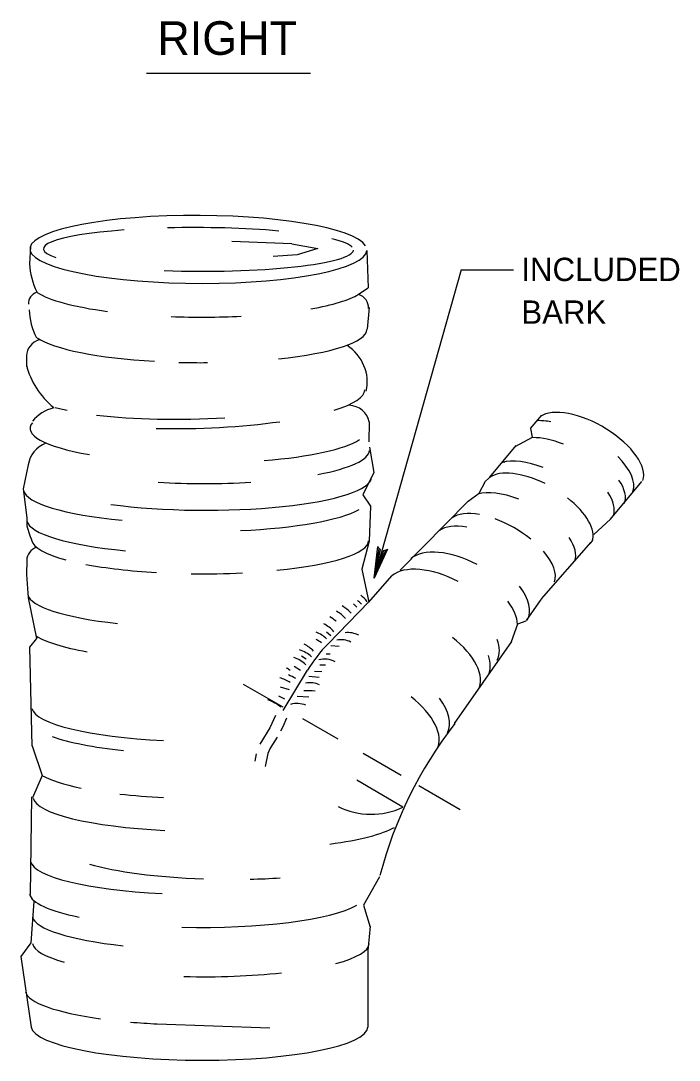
# Model space of a CAD drawing. Extents: x 639115 to 640019, y 298285 to 298879.
# Drawn here: x 639717.2 to 639801.9, y 298555.3 to 298689.1 of the extents above; entities that cross this region are included whole.
import ezdxf

# ---------------------------------------------------------------- set-up
doc = ezdxf.new("R2010")
doc.units = 0
doc.layers.add('1', color=7, linetype='Continuous')

msp = doc.modelspace()

# ---------------------------------------------------------------- linework, layer by layer
at = {"layer": '1'}
for p, q in [((639733.43, 298682.34), (639754.53, 298682.34)), ((639752.13, 298660.35), (639744.38, 298660.67)), ((639773.91, 298657.04), (639762.7, 298617.37)), ((639773.91, 298657.04), (639780.61, 298657.04)), ((639760.69, 298653.88), (639761.95, 298654.7)), ((639782.81, 298636.59), (639784.26, 298638.32)), ((639783.07, 298635.51), (639782.84, 298636.61)), ((639780.86, 298634.29), (639783.07, 298635.51)), ((639777.59, 298630.35), (639780.99, 298634.41)), ((639793.1, 298624.94), (639797.15, 298629.78)), ((639793.1, 298624.94), (639790.95, 298622.98)), ((639784.23, 298614.69), (639790.62, 298621.99)), ((639790.48, 298621.8), (639790.82, 298622.21)), ((639756.77, 298608.92), (639762, 298614.3)), ((639760.05, 298614.05), (639760.49, 298613.63)), ((639782.3, 298611.91), (639784.19, 298614.63)), ((639780.36, 298609.19), (639781.17, 298611.47)), ((639781.17, 298611.47), (639782.25, 298611.88)), ((639756.59, 298610.47), (639757.13, 298609.99)), ((639757.11, 298608.68), (639758.19, 298608.61)), ((639773.06, 298598.64), (639780.4, 298609.19)), ((639753.36, 298607.36), (639753.96, 298606.98)), ((639756.51, 298607.62), (639757.03, 298607.62)), ((639752.4, 298606.05), (639753.21, 298605.52)), ((639755.73, 298606.21), (639756.44, 298606.21)), ((639750.99, 298600.32), (639754.14, 298605.54)), ((639754.29, 298604.74), (639755.62, 298604.64)), ((639755.01, 298605.41), (639755.98, 298605.33)), ((639750.98, 298600.76), (639745.9, 298603.69)), ((639750.59, 298603.38), (639751.76, 298603.05)), ((639750.38, 298602.21), (639751.15, 298601.83)), ((639752.79, 298602.17), (639754.3, 298602.11)), ((639758.07, 298596.66), (639753.54, 298599.27)), ((639766.16, 298591.98), (639761.28, 298594.79)), ((639766.41, 298587.88), (639760.46, 298591.38)), ((639773.77, 298587.57), (639768.45, 298590.65)), ((639763.37, 298578.93), (639761.34, 298575.27)), ((639761.34, 298575.27), (639762.2, 298572.46)), ((639734.8, 298560.02), (639749.29, 298559.49))]:
    msp.add_line(p, q, dxfattribs=at)
for points in [[(639718.47, 298660.01), (639718.38, 298657.8)], [(639752.13, 298660.35), (639755.46, 298659.76), (639752.78, 298658.96), (639749.69, 298658.74)], [(639761.77, 298659.49), (639761.95, 298654.7)], [(639762.04, 298652.18), (639761.79, 298649.37)], [(639717.96, 298645.97), (639717.98, 298644.54)], [(639762.06, 298637.46), (639762.03, 298634.9)], [(639762.1, 298634.21), (639762.66, 298630.96), (639761.25, 298628.06), (639762.23, 298626.64), (639762.06, 298622.13), (639761.12, 298618.51), (639762.02, 298614.29)], [(639718.21, 298631.94), (639717.55, 298628.84), (639718.01, 298625.13), (639718.01, 298624.03)], [(639766.05, 298618.38), (639774.81, 298627.25), (639776.23, 298628.27), (639777.04, 298629.82), (639777.79, 298630.52)], [(639764.21, 298620.95), (639763.9, 298620.89), (639762.7, 298617.37), (639764.21, 298620.95), (639764.43, 298621.09), (639762.7, 298617.37), (639763.53, 298620.99), (639763.3, 298621.19), (639762.7, 298617.37), (639763.18, 298621.45), (639763.3, 298621.19)], [(639718, 298619.66), (639717.99, 298617.81), (639718.19, 298614.81), (639719.27, 298609.6), (639718.37, 298608.46), (639718.68, 298595.76)], [(639762.02, 298614.29), (639764.97, 298617.66)], [(639750.03, 298599.68), (639749.28, 298598.11), (639748, 298595.98)], [(639751.41, 298599.35), (639750.97, 298598.21), (639750.67, 298597.68)], [(639750.22, 298596.89), (639749.32, 298595.5), (639749.02, 298594.82), (639748.67, 298593.14)], [(639718.71, 298595.77), (639720.01, 298591.95), (639718.75, 298589.1)], [(639747.53, 298594.76), (639747.34, 298593.83)], [(639718.61, 298589.22), (639718.44, 298576.65)], [(639718.93, 298575.76), (639718.53, 298570.43), (639717.24, 298568.68), (639718.56, 298559.6)], [(639761.88, 298568.99), (639761.88, 298559.6)]]:
    msp.add_lwpolyline(points, dxfattribs=at)
for centre, major_axis, ratio, start_param, end_param in [((639740.09, 298659.65), (21.67, -0.08), 0.201648, 0.122701, 6.273719), ((639740.09, 298659.65), (19.94, -0.07), 0.140896, 2.070785, 3.54742), ((639740.09, 298659.65), (19.94, -0.07), 0.140896, 1.026558, 1.771582), ((639740.09, 298659.65), (19.94, -0.07), 0.140896, 0.122755, 0.53432), ((639740.09, 298659.65), (19.94, -0.07), 0.140896, 4.489929, 6.273772), ((639728.49, 298658.02), (-10.11, 0), 0.9025, 0.023891, 0.433959), ((639719.9, 298652.73), (-1.67, 0), 0.9025, 5.088241, 6.356756), ((639740.1, 298655.31), (21.67, -0.08), 0.201648, 3.437197, 4.143226), ((639740.1, 298655.31), (21.67, -0.08), 0.201648, 5.442821, 5.966342), ((639759.97, 298652.19), (2, 0), 0.9025, 6.209615, 7.47813), ((639728.44, 298652.11), (-10.11, 0), 0.9025, 0.023891, 0.433959), ((639740.1, 298655.31), (21.67, -0.08), 0.201648, 4.549477, 4.968721), ((639740.1, 298649.45), (21.67, -0.08), 0.201648, 5.20727, 6.273719), ((639720.45, 298645.92), (-2.48, 0), 0.9025, 5.058523, 6.264565), ((639740.1, 298649.45), (21.67, -0.08), 0.201648, 3.432131, 4.449047), ((639755.3, 298642.6), (6.52, 0), 0.9025, 6.079323, 7.21363), ((639729, 298646.9), (-11.27, 0), 0.9025, 0.209985, 0.841717), ((639740.1, 298649.45), (21.67, -0.08), 0.201648, 4.596429, 4.766623), ((639739.84, 298641), (21.66, 0.6), 0.201683, 5.665679, 6.275226), ((639722.79, 298634.96), (-4.94, 0), 0.9025, 4.977364, 5.666936), ((639739.78, 298642.21), (21.66, 0.6), 0.201683, 3.716025, 3.83676), ((639759.29, 298637.09), (2.8, 0), 0.9025, 0.147707, 1.509991), ((639790.34, 298633.6), (6.79, -3.97), 0.467565, 0.082974, 2.935197), ((639739.78, 298642.21), (21.66, 0.6), 0.201683, 4.074018, 4.879012), ((639740.1, 298636.54), (21.67, -0.08), 0.201648, 2.973143, 4.010085), ((639739.84, 298641), (21.66, 0.6), 0.201683, 4.464238, 5.224131), ((639788, 298632.54), (6.79, -3.97), 0.467565, 2.208713, 2.489954), ((639740.1, 298636.54), (21.67, -0.08), 0.201648, 5.113839, 5.986294), ((639787.37, 298630.35), (6.79, -3.97), 0.467565, 1.880941, 2.489954), ((639722.07, 298631.52), (-3.89, 0), 0.9025, 5.133197, 6.163121), ((639740.43, 298633.9), (21.67, -0.08), 0.201648, 5.479737, 6.273719), ((639784.76, 298627.34), (6.79, -3.97), 0.467565, 1.880941, 2.748947), ((639789.08, 298632.22), (6.79, -3.97), 0.467565, 0.082974, 1.055649), ((639783.85, 298625.79), (6.79, -3.97), 0.467565, 1.718853, 2.935197), ((639779.99, 298631.8), (-0.72, 0), 0.9025, 5.534807, 5.562504), ((639740.7, 298630.46), (21.67, -0.08), 0.201648, 4.132872, 6.273719), ((639788, 298630.67), (6.79, -3.97), 0.467565, 0.082974, 0.759294), ((639739.24, 298628.76), (21.67, -0.08), 0.201648, 3.185754, 4.28703), ((639740.43, 298633.9), (21.67, -0.08), 0.201648, 4.454879, 5.012612), ((639781.6, 298623.27), (6.79, -3.97), 0.467565, 1.880941, 2.748947), ((639786.56, 298629.13), (6.79, -3.97), 0.467565, 0.082974, 0.759294), ((639783.85, 298625.79), (6.79, -3.97), 0.467565, 0.082974, 1.279583), ((639740.43, 298627.75), (21.67, -0.08), 0.201648, 4.950205, 5.932829), ((639778.99, 298620.58), (6.79, -3.97), 0.467565, 2.239501, 2.935197), ((639739.67, 298624.83), (21.67, -0.08), 0.201648, 3.185754, 4.28703), ((639778.99, 298620.58), (6.79, -3.97), 0.467565, 1.25877, 1.939358), ((639757.78, 298634.04), (-41.27, 0), 0.9025, 0.270734, 0.332504), ((639777.36, 298618.96), (6.79, -3.97), 0.467565, 2.239501, 2.935197), ((639740.32, 298622.29), (21.67, -0.08), 0.201648, 3.185754, 3.790997), ((639740.32, 298622.29), (21.67, -0.08), 0.201648, 5.186102, 6.273719), ((639781.6, 298623.27), (6.79, -3.97), 0.467565, 0.082974, 0.759294), ((639720.07, 298619.62), (-2.06, 0), 0.9025, 5.11957, 6.257282), ((639774.21, 298615.02), (7.36, -4.18), 0.522825, 1.630807, 2.949997), ((639778.99, 298620.58), (6.79, -3.97), 0.467565, 0.082974, 0.94294), ((639740.32, 298622.29), (21.67, -0.08), 0.201648, 3.9671, 4.450313), ((639740.32, 298622.29), (21.67, -0.08), 0.201648, 4.659967, 4.966185), ((639771.77, 298612.82), (7.36, -4.18), 0.522825, 1.630807, 2.949997), ((639739.78, 298615.36), (21.67, -0.08), 0.201648, 3.185754, 4.229446), ((639758.02, 298612.08), (4.52, 0), 0.9025, 0.581699, 0.855632), ((639775.02, 298616.08), (7.36, -4.18), 0.522825, 0.012147, 0.872985), ((639756.19, 298610.32), (4.52, 0), 0.9025, 0.6688, 1.012361), ((639757.6, 298611.4), (4.52, 0), 0.9025, 0.690303, 0.855632), ((639773.49, 298614.12), (7.36, -4.18), 0.522825, 0.336987, 0.872985), ((639784.8, 298614.29), (-0.72, 0), 0.9025, 5.614496, 5.722494), ((639754.66, 298608.89), (4.52, 0), 0.9025, 0.80175, 1.02114), ((639755.48, 298609.64), (4.52, 0), 0.9025, 0.6688, 1.012361), ((639753.98, 298607.94), (4.52, 0), 0.9025, 0.6688, 1.052971), ((639739.88, 298611.16), (21.67, -0.08), 0.201648, 3.453358, 4.005332), ((639753.53, 298606.91), (4.23, 0), 0.9025, 0.762645, 1.156681), ((639759.31, 298607.85), (-2.78, 0), 0.9025, 4.17402, 4.840238), ((639768.71, 298607.13), (7.36, -4.18), 0.522825, 0.012147, 1.302069), ((639751.48, 298605.31), (4.52, 0), 0.9025, 0.715614, 1.056065), ((639772.35, 298596.57), (-20.74, 0), 0.9025, 5.562504, 5.783791), ((639752.91, 298605.98), (4.52, 0), 0.9025, 0.840967, 1.030064), ((639758.42, 298606.92), (-2.78, 0), 0.9025, 4.228287, 4.903228), ((639771.14, 298610.95), (7.36, -4.18), 0.522825, 0.012147, 0.563017), ((639750.63, 298603.41), (4.52, 0), 0.9025, 0.757043, 1.172134), ((639751.54, 298604.3), (4.52, 0), 0.9025, 0.81049, 1.215592), ((639756.3, 298604.43), (-2.78, 0), 0.9025, 4.195457, 4.977245), ((639769.97, 298609), (7.36, -4.18), 0.522825, 0.012147, 0.545239), ((639748.41, 298601.73), (5.43, 0), 0.9025, 0.872778, 0.978202), ((639749.22, 298600.64), (4.52, 0), 0.9025, 0.931576, 1.271823), ((639749.53, 298600.41), (5.43, 0), 0.9025, 0.965958, 1.166295), ((639754.43, 298601.39), (-2.78, 0), 0.9025, 4.250219, 4.910831), ((639746.52, 298596.28), (6.51, 0), 0.9025, 0.865849, 1.179086), ((639754.17, 298597.8), (-5.62, 0), 0.9025, 4.545654, 4.802236), ((639763.39, 298599.48), (7.36, -4.18), 0.522825, 0.012147, 1.302069), ((639764.74, 298601.59), (7.36, -4.18), 0.522825, 0.012147, 0.883314), ((639740.32, 298600.71), (21.67, -0.08), 0.201648, 3.185754, 4.494175), ((639752.76, 298598.72), (-2.78, 0), 0.9025, 4.283943, 5.01022), ((639824.69, 298566.24), (62.88, 0), 0.9025, 2.533992, 2.913047), ((639740.17, 298599.06), (21.67, -0.08), 0.201648, 3.654019, 4.248787), ((639740.32, 298593.39), (21.67, -0.08), 0.201648, 3.493127, 3.928513), ((639740.5, 298589.16), (21.67, -0.08), 0.201648, 3.185754, 4.494175), ((639740.32, 298593.39), (21.67, -0.08), 0.201648, 4.215674, 4.494175), ((639762.33, 298594.99), (8.87, 0), 0.9025, 4.212296, 5.190862), ((639744.87, 298586.82), (21.67, -0.08), 0.201648, 5.306906, 5.946377), ((639740.14, 298581.03), (21.67, -0.08), 0.201648, 3.185754, 4.494175), ((639743.99, 298582.98), (21.67, -0.08), 0.201648, 3.740884, 4.562247), ((639743.99, 298582.98), (21.67, -0.08), 0.201648, 4.840137, 5.023005), ((639740.03, 298576.8), (21.67, -0.08), 0.201648, 3.185754, 3.931551), ((639740.03, 298576.8), (21.67, -0.08), 0.201648, 4.618388, 5.946377), ((639740.39, 298573.91), (21.67, -0.08), 0.201648, 3.185754, 4.235618), ((639824.69, 298566.24), (62.88, 0), 0.9025, 3.02963, 3.093128), ((639740.39, 298570.45), (21.67, -0.08), 0.201648, 3.185754, 3.76911), ((639740.39, 298570.45), (21.67, -0.08), 0.201648, 5.644445, 6.273719), ((639740.39, 298570.45), (21.67, -0.08), 0.201648, 4.611978, 5.212304), ((639739.51, 298564.27), (21.67, -0.08), 0.201648, 3.185754, 4.124963), ((639739.51, 298564.27), (21.67, -0.08), 0.201648, 4.32801, 4.494175), ((639740.21, 298559.71), (21.67, -0.08), 0.201648, 3.185754, 6.273719)]:
    msp.add_ellipse(centre, major_axis=major_axis, ratio=ratio, start_param=start_param, end_param=end_param, dxfattribs=at)

# ---------------------------------------------------------------- texts
for s, height, p in [('RIGHT', 4.32, (639734.81, 298684.68)), ('INCLUDED', 3, (639781.64, 298655.58)), ('BARK', 3, (639781.64, 298650.08))]:
    msp.add_text(s, height=height, dxfattribs=at).set_placement(p)

doc.saveas('drawing.dxf')
